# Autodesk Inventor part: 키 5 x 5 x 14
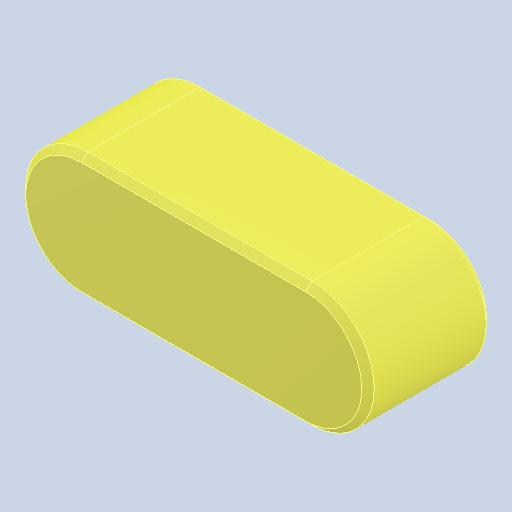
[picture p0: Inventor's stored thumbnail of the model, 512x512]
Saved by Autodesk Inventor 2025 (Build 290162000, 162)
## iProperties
Created: 2024-07
Part Number: 키 5 x 5 x 14
Material: 강철, 연강
Description: 키 및 해당 키홈
Document SubType Name: Modeling
Designer: SAMSUNG
Density: 7.85 g/cm^3
Appearance: 기본값
Author: jhkim
Sending System: Autodesk Inventor 2025
Preprocessor: ST-DEVELOPER v20
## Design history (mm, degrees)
feature "Solid1"
node "솔리드1"
